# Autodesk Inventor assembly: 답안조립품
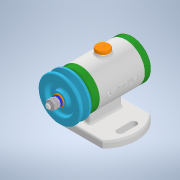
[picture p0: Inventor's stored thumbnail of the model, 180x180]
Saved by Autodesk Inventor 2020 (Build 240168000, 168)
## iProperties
Created: 2021-09
Part Number: 답안조립품
Document SubType Name: Assembly
Designer: Administrator
Author: Administrator
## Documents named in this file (14)
- C:\Users\Administrator\Desktop\710906V1014\답안조립품.iam
- C:\Users\Administrator\Desktop\710906V1014\본체.ipt
- C:\Users\Administrator\Desktop\710906V1014\앞커버.ipt
- C:\Users\Administrator\Desktop\710906V1014\뒤커버.ipt
- C:\Users\Administrator\Desktop\710906V1014\오일 실 15x25x7.ipt
- C:\Users\Administrator\Desktop\710906V1014\베어링 15x32x9.ipt
- C:\Users\Administrator\Desktop\710906V1014\축.ipt
- C:\Users\Administrator\Desktop\710906V1014\볼트 M4x12.ipt
- C:\Users\Administrator\Desktop\710906V1014\캡.ipt
- C:\Users\Administrator\Desktop\710906V1014\키 3x3.ipt
- C:\Users\Administrator\Desktop\710906V1014\V벨트풀리.ipt
- C:\Users\Administrator\Desktop\710906V1014\와셔 8x17.ipt
- C:\Users\Administrator\Desktop\710906V1014\스프링와셔 8.ipt
- C:\Users\Administrator\Desktop\710906V1014\너트 M8.ipt
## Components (1 placed, 1 different names)
1. V벨트풀리:1
